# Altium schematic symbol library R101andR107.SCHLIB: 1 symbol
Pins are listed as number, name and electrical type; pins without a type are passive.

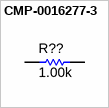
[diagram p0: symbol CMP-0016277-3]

## CMP-0016277-3
designator R??, comment ValueDisplayed: 1.00k  (hidden comment: CRCW20101K00FKEF)
RES, 1.00 k, 1%, 0.75 W, AEC-Q200 Grade 0, 2010; Manufacturer: Vishay-Dale; Power_W: 750mW; TempCo: 100 ppm/C; Value_Code: 1k00; Value: 1.00k; EIA_Code: E96; Res_ohm: 1k; SizeX_mm: 5; SizeY_mm: 2.5; SizeZ_mm: 1.66; Value2: 0.75W; SizeArea_mm2: 12.5; CompType: Resistor; AEC Qualified: Y; VDC_V: 400V; AEC Grade: 0; AEC Category: Q200
footprint 0402 (0402 from SM-752 data)
pins: 1, 2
